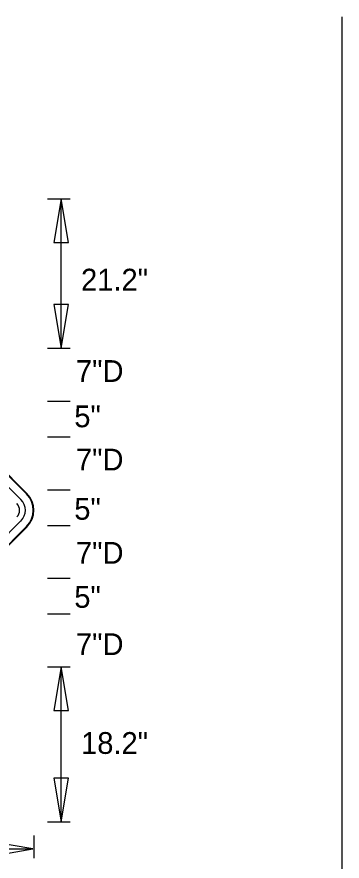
# Model space of a CAD drawing. Extents: x 0 to 770, y 0 to 495.
# Drawn here: x 332.7 to 385, y 359.3 to 495 of the extents above; entities that cross this region are included whole.
import ezdxf

# ---------------------------------------------------------------- set-up
doc = ezdxf.new("R2010")
doc.units = 0
for name, color, linetype in [('Dimension', 7, 'Continuous'), ('GSBWFill', 7, 'Continuous'), ('GSColorFill', 7, 'Continuous'), ('GSDims', 7, 'Continuous'), ('SheetLines_dp', 7, 'Continuous'), ('TextStructures', 7, 'Continuous')]:
    doc.layers.add(name, color=color, linetype=linetype)

msp = doc.modelspace()

# ---------------------------------------------------------------- linework, layer by layer
at = {"layer": 'Dimension'}
for points in [[(339.8, 465.76), (338.61, 458.74), (340.99, 458.74)], [(339.8, 441.71), (340.99, 448.73), (338.61, 448.73)], [(339.8, 390.49), (338.61, 383.47), (340.99, 383.47)], [(339.8, 365.58), (340.99, 372.6), (338.61, 372.6)], [(335.24, 361.21), (328.22, 362.39), (328.22, 360.02)]]:
    msp.add_lwpolyline(points, close=True, dxfattribs=at)
at = {"layer": 'GSBWFill'}
for p, q in [((334.3, 418.36), (288.02, 464.64)), ((333.33, 417.39), (287.05, 463.67)), ((287.06, 367.67), (333.33, 413.95)), ((288.02, 366.7), (334.3, 412.98))]:
    msp.add_line(p, q, dxfattribs=at)
for radius in [3.81, 1.52, 2.44]:
    msp.add_arc((331.61, 415.67), radius, 315, 45, dxfattribs=at)
at = {"layer": 'GSColorFill'}
for p, q in [((287.95, 464.58), (334.23, 418.3)), ((334.3, 418.36), (288.02, 464.64)), ((333.33, 417.39), (287.05, 463.67)), ((287.06, 367.67), (333.33, 413.95)), ((334.23, 413.05), (287.95, 366.76)), ((288.02, 366.7), (334.3, 412.98))]:
    msp.add_line(p, q, dxfattribs=at)
for radius in [3.71, 3.81, 1.52, 2.44]:
    msp.add_arc((331.61, 415.67), radius, 315, 45, dxfattribs=at)
at = {"layer": 'GSDims'}
for p, q in [((337.61, 465.76), (341.26, 465.76)), ((339.8, 441.71), (339.8, 465.76)), ((337.61, 441.71), (341.26, 441.71)), ((337.61, 441.71), (341.26, 441.71)), ((337.61, 433.21), (341.26, 433.21)), ((337.61, 433.21), (341.26, 433.21)), ((337.61, 427.48), (341.26, 427.48)), ((337.61, 427.48), (341.26, 427.48)), ((337.61, 418.97), (341.26, 418.97)), ((337.61, 418.97), (341.26, 418.97)), ((337.61, 413.24), (341.26, 413.24)), ((337.61, 413.24), (341.26, 413.24)), ((337.61, 404.73), (341.26, 404.73)), ((337.61, 404.73), (341.26, 404.73)), ((337.61, 399), (341.26, 399)), ((337.61, 399), (341.26, 399)), ((337.61, 390.49), (341.26, 390.49)), ((337.61, 390.49), (341.26, 390.49)), ((339.8, 365.58), (339.8, 390.49)), ((337.61, 365.58), (341.26, 365.58)), ((335.41, 363.39), (335.41, 359.74)), ((235.24, 361.21), (335.24, 361.21))]:
    msp.add_line(p, q, dxfattribs=at)
at = {"layer": 'SheetLines_dp'}
msp.add_line((385, 0), (385, 495), dxfattribs=at)

# ---------------------------------------------------------------- texts
at = {"layer": 'TextStructures'}
for s, p in [('21.2"', (343.01, 451)), ('7"D', (342.19, 436.31)), ('5"', (341.92, 429.02)), ('7"D', (342.19, 422.07)), ('5"', (341.92, 414.15)), ('7"D', (342.19, 407.07)), ('5"', (341.92, 399.99)), ('7"D', (342.19, 392.39)), ('18.2"', (343.01, 376.5))]:
    msp.add_text(s, height=3.5, dxfattribs=at).set_placement(p)

doc.saveas('drawing.dxf')
